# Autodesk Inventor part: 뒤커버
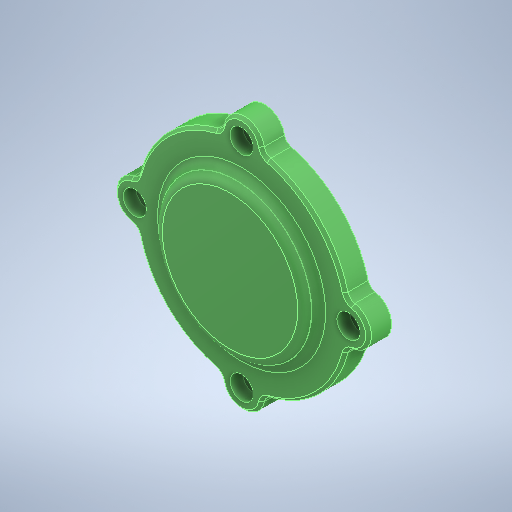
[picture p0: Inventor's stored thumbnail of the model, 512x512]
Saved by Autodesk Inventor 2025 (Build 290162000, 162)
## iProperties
Created: 2024-08
Part Number: 뒤커버
Material: 알루미늄 6061
Document SubType Name: Modeling
Designer: 학생
Density: 2.71 g/cm^3
Appearance: 기본값
Company: 한국ATC센터
Author: jhkim
Sending System: Autodesk Inventor 2025
Preprocessor: ST-DEVELOPER v20
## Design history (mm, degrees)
feature "솔리드1"
node "솔리드2"
